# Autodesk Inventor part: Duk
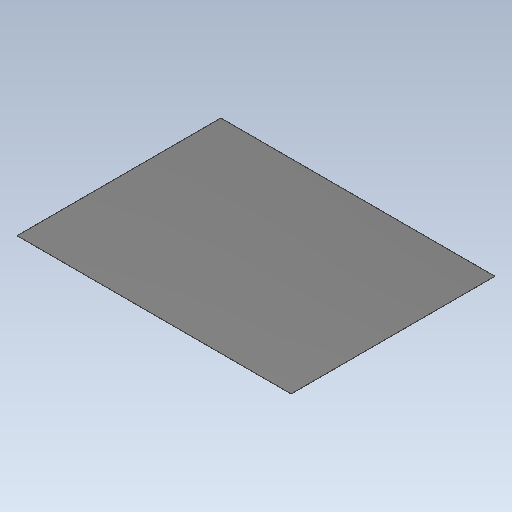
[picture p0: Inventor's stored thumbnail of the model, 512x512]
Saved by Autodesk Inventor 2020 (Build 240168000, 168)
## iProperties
Created: 2019-06
Part Number: Duk
Material: Acetal Resin, Black
Document SubType Name: Modeling
Designer: cl
Density: 1.425 g/cm^3
Appearance: Smooth - Black
Author: cl
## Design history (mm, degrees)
sketch "Sketch1"
  geometry: L1 (0, 0)-(2690, 0); L2 (2690, 0)-(2690, -2000); L3 (2690, -2000)-(0, -2000); L4 (0, -2000)-(0, 0)
  constraints: 8 end point, 2 parallel, 1 horizontal, 1 perpendicular
  dimensions: "d0" = 2690 distance of L2.end L3.end (computed from Daghöjd); "d1" = 2000 distance of L3.end L1.start (= Dagbredd)
extrude "Extrusion1" new body sketch "Sketch1" distance "d2" = 1.5; taper "d3" = 0 deg
body "Solid1"
other parameters: "Dagbredd" = 2000
